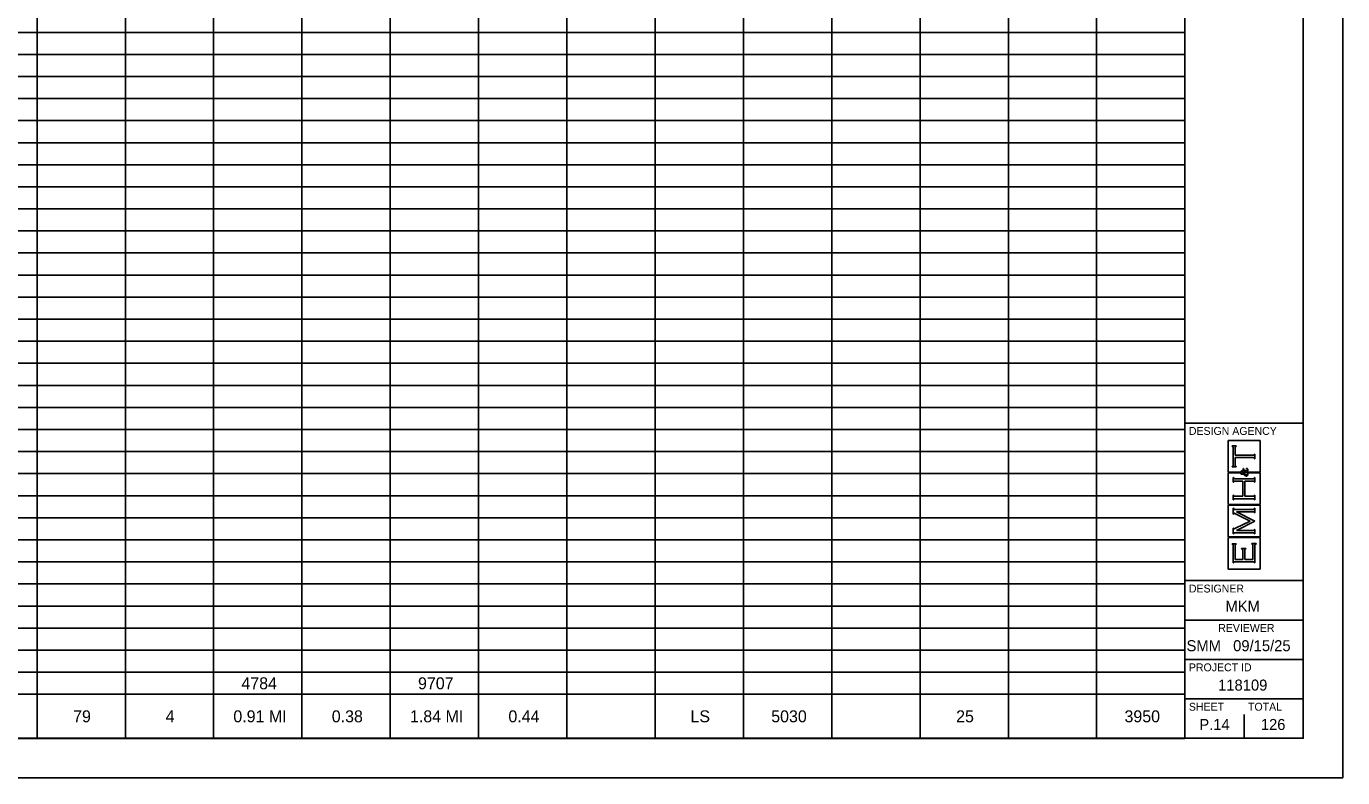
# Model space of a CAD drawing. Extents: x 0 to 34, y 0 to 22.
# Drawn here: x 17.31 to 34, y 0 to 9.53 of the extents above; entities that cross this region are included whole.
import ezdxf

# ---------------------------------------------------------------- set-up
doc = ezdxf.new("R2010")
doc.units = 0
for name, color, linetype in [('Default', 7, 'Continuous'), ('SH_Border', 7, 'Continuous'), ('SH_Cut_Line', 7, 'Continuous'), ('SH_Data', 7, 'Continuous')]:
    doc.layers.add(name, color=color, linetype=linetype)

msp = doc.modelspace()

# ---------------------------------------------------------------- linework, layer by layer
at = {"layer": 'Default'}
for p, q in [((17.442, 21.496), (17.442, 0.498)), ((18.562, 21.496), (18.562, 0.498)), ((19.681, 21.496), (19.681, 0.498)), ((20.801, 21.496), (20.801, 0.498)), ((21.921, 21.496), (21.921, 0.498)), ((23.041, 21.496), (23.041, 0.498)), ((24.161, 21.496), (24.161, 0.498)), ((25.281, 21.496), (25.281, 0.498)), ((26.401, 21.496), (26.401, 0.498)), ((27.521, 21.496), (27.521, 0.498)), ((28.64, 21.496), (28.64, 0.498)), ((29.76, 21.496), (29.76, 0.498)), ((30.88, 21.496), (30.88, 0.498)), ((32, 21.496), (32, 0.498)), ((1.5, 9.457), (32, 9.457)), ((1.5, 9.177), (32, 9.177)), ((1.5, 8.897), (32, 8.897)), ((1.5, 8.617), (32, 8.617)), ((1.5, 8.337), (32, 8.337)), ((1.5, 8.057), (32, 8.057)), ((1.5, 7.777), (32, 7.777)), ((1.5, 7.498), (32, 7.498)), ((1.5, 7.218), (32, 7.218)), ((1.5, 6.938), (32, 6.938)), ((1.5, 6.658), (32, 6.658)), ((1.5, 6.378), (32, 6.378)), ((1.5, 6.098), (32, 6.098)), ((1.5, 5.818), (32, 5.818)), ((1.5, 5.538), (32, 5.538)), ((1.5, 5.258), (32, 5.258)), ((1.5, 4.978), (32, 4.978)), ((1.5, 4.698), (32, 4.698)), ((1.5, 4.418), (32, 4.418)), ((1.5, 4.138), (32, 4.138)), ((1.5, 3.858), (32, 3.858)), ((1.5, 3.578), (32, 3.578)), ((1.5, 3.298), (32, 3.298)), ((1.5, 3.018), (32, 3.018)), ((1.5, 2.738), (32, 2.738)), ((1.5, 2.458), (32, 2.458)), ((1.5, 2.178), (32, 2.178)), ((1.5, 1.898), (32, 1.898)), ((1.5, 1.618), (32, 1.618)), ((1.5, 1.338), (32, 1.338)), ((1.5, 1.058), (32, 1.058)), ((1.5, 0.498), (32, 0.498))]:
    msp.add_line(p, q, dxfattribs=at)
at = {"layer": 'SH_Border'}
for p, q in [((32, 0.5), (32, 21.5)), ((32, 4.5), (33.5, 4.5)), ((32, 2.5), (33.5, 2.5)), ((32, 2), (33.5, 2)), ((32, 1.5), (33.5, 1.5)), ((32, 1), (33.5, 1))]:
    msp.add_line(p, q, dxfattribs=at)
msp.add_lwpolyline([(1.5, 21.5), (33.5, 21.5), (33.5, 0.5), (1.5, 0.5)], close=True, dxfattribs=at)
at = {"layer": 'SH_Cut_Line'}
msp.add_lwpolyline([(0, 0), (34, 0), (34, 22), (0, 22)], close=True, dxfattribs=at)
at = {"layer": 'SH_Data'}
for p, q in [((32.952, 4.279), (32.547, 4.279)), ((32.547, 4.279), (32.547, 3.875)), ((32.598, 4.204), (32.598, 4.211)), ((32.598, 4.211), (32.65, 4.211)), ((32.603, 4.203), (32.598, 4.204)), ((32.606, 4.201), (32.603, 4.203)), ((32.608, 4.199), (32.606, 4.201)), ((32.61, 4.196), (32.608, 4.199)), ((32.611, 4.192), (32.61, 4.196)), ((32.611, 4.187), (32.611, 4.192)), ((32.611, 3.968), (32.611, 4.187)), ((32.638, 4.196), (32.637, 4.192)), ((32.637, 4.192), (32.637, 4.187)), ((32.637, 4.187), (32.637, 4.093)), ((32.64, 4.199), (32.638, 4.196)), ((32.642, 4.201), (32.64, 4.199)), ((32.645, 4.203), (32.642, 4.201)), ((32.65, 4.204), (32.645, 4.203)), ((32.65, 4.211), (32.65, 4.204)), ((32.952, 3.875), (32.952, 4.279)), ((32.637, 4.093), (32.864, 4.093)), ((32.864, 4.061), (32.637, 4.061)), ((32.637, 4.061), (32.637, 3.968)), ((32.864, 4.093), (32.869, 4.093)), ((32.87, 4.061), (32.864, 4.061)), ((32.869, 4.093), (32.873, 4.094)), ((32.874, 4.06), (32.87, 4.061)), ((32.873, 4.094), (32.876, 4.096)), ((32.876, 4.059), (32.874, 4.06)), ((32.876, 4.096), (32.878, 4.097)), ((32.878, 4.057), (32.876, 4.059)), ((32.878, 4.097), (32.88, 4.101)), ((32.88, 4.053), (32.878, 4.057)), ((32.88, 4.101), (32.881, 4.106)), ((32.881, 4.048), (32.88, 4.053)), ((32.881, 4.106), (32.888, 4.106)), ((32.888, 4.048), (32.881, 4.048)), ((32.888, 4.106), (32.888, 4.048)), ((32.547, 3.875), (32.696, 3.875)), ((32.696, 3.869), (32.547, 3.869)), ((32.547, 3.869), (32.547, 3.465)), ((32.598, 3.95), (32.603, 3.951)), ((32.598, 3.944), (32.598, 3.95)), ((32.65, 3.944), (32.598, 3.944)), ((32.603, 3.951), (32.606, 3.953)), ((32.606, 3.953), (32.608, 3.955)), ((32.608, 3.955), (32.61, 3.958)), ((32.61, 3.958), (32.611, 3.962)), ((32.611, 3.962), (32.611, 3.968)), ((32.637, 3.968), (32.637, 3.962)), ((32.637, 3.962), (32.638, 3.958)), ((32.638, 3.958), (32.64, 3.955)), ((32.64, 3.955), (32.642, 3.953)), ((32.642, 3.953), (32.645, 3.951)), ((32.645, 3.951), (32.65, 3.95)), ((32.65, 3.95), (32.65, 3.944)), ((32.696, 3.875), (32.696, 3.869)), ((32.703, 3.879), (32.705, 3.883)), ((32.703, 3.873), (32.703, 3.879)), ((32.703, 3.868), (32.703, 3.873)), ((32.705, 3.863), (32.703, 3.868)), ((32.705, 3.883), (32.708, 3.887)), ((32.708, 3.858), (32.705, 3.863)), ((32.708, 3.887), (32.711, 3.89)), ((32.709, 3.879), (32.708, 3.876)), ((32.708, 3.876), (32.708, 3.873)), ((32.708, 3.873), (32.708, 3.869)), ((32.708, 3.869), (32.71, 3.866)), ((32.712, 3.853), (32.708, 3.858)), ((32.712, 3.881), (32.709, 3.879)), ((32.71, 3.866), (32.712, 3.864)), ((32.711, 3.89), (32.715, 3.892)), ((32.714, 3.883), (32.712, 3.881)), ((32.712, 3.864), (32.715, 3.862)), ((32.718, 3.85), (32.712, 3.853)), ((32.716, 3.884), (32.714, 3.883)), ((32.715, 3.892), (32.72, 3.892)), ((32.715, 3.862), (32.718, 3.861)), ((32.72, 3.884), (32.716, 3.884)), ((32.718, 3.861), (32.721, 3.861)), ((32.726, 3.85), (32.718, 3.85)), ((32.72, 3.892), (32.725, 3.892)), ((32.724, 3.884), (32.72, 3.884)), ((32.721, 3.861), (32.723, 3.861)), ((32.723, 3.861), (32.725, 3.862)), ((32.728, 3.882), (32.724, 3.884)), ((32.725, 3.892), (32.729, 3.89)), ((32.725, 3.862), (32.728, 3.862)), ((32.729, 3.85), (32.726, 3.85)), ((32.731, 3.88), (32.728, 3.882)), ((32.728, 3.862), (32.731, 3.863)), ((32.729, 3.89), (32.732, 3.887)), ((32.731, 3.85), (32.729, 3.85)), ((32.734, 3.877), (32.731, 3.88)), ((32.731, 3.863), (32.735, 3.865)), ((32.734, 3.851), (32.731, 3.85)), ((32.732, 3.887), (32.736, 3.883)), ((32.737, 3.872), (32.734, 3.877)), ((32.737, 3.852), (32.734, 3.851)), ((32.735, 3.865), (32.74, 3.867)), ((32.736, 3.883), (32.74, 3.878)), ((32.74, 3.867), (32.737, 3.872)), ((32.741, 3.853), (32.737, 3.852)), ((32.738, 3.893), (32.738, 3.922)), ((32.738, 3.922), (32.741, 3.922)), ((32.741, 3.893), (32.738, 3.893)), ((32.74, 3.878), (32.744, 3.869)), ((32.741, 3.922), (32.741, 3.918)), ((32.741, 3.918), (32.742, 3.915)), ((32.742, 3.896), (32.741, 3.895)), ((32.741, 3.895), (32.741, 3.893)), ((32.746, 3.855), (32.741, 3.853)), ((32.742, 3.915), (32.743, 3.913)), ((32.743, 3.897), (32.742, 3.896)), ((32.743, 3.913), (32.745, 3.911)), ((32.745, 3.899), (32.743, 3.897)), ((32.744, 3.869), (32.754, 3.875)), ((32.745, 3.911), (32.749, 3.908)), ((32.746, 3.899), (32.745, 3.899)), ((32.748, 3.899), (32.746, 3.899)), ((32.752, 3.844), (32.746, 3.855)), ((32.755, 3.899), (32.748, 3.899)), ((32.749, 3.908), (32.756, 3.904)), ((32.756, 3.86), (32.751, 3.857)), ((32.751, 3.857), (32.754, 3.852)), ((32.757, 3.837), (32.752, 3.844)), ((32.754, 3.875), (32.764, 3.881)), ((32.754, 3.852), (32.757, 3.848)), ((32.763, 3.895), (32.755, 3.899)), ((32.756, 3.904), (32.763, 3.9)), ((32.761, 3.863), (32.756, 3.86)), ((32.757, 3.848), (32.761, 3.845)), ((32.764, 3.865), (32.761, 3.863)), ((32.761, 3.845), (32.765, 3.843)), ((32.763, 3.9), (32.77, 3.896)), ((32.772, 3.887), (32.763, 3.895)), ((32.764, 3.881), (32.772, 3.887)), ((32.768, 3.867), (32.764, 3.865)), ((32.765, 3.843), (32.769, 3.841)), ((32.774, 3.872), (32.768, 3.867)), ((32.769, 3.841), (32.773, 3.841)), ((32.77, 3.896), (32.776, 3.891)), ((32.773, 3.841), (32.778, 3.841)), ((32.782, 3.878), (32.774, 3.872)), ((32.776, 3.891), (32.781, 3.895)), ((32.778, 3.841), (32.782, 3.843)), ((32.779, 3.923), (32.781, 3.926)), ((32.782, 3.922), (32.779, 3.923)), ((32.781, 3.926), (32.787, 3.924)), ((32.781, 3.895), (32.784, 3.898)), ((32.785, 3.921), (32.782, 3.922)), ((32.786, 3.873), (32.782, 3.878)), ((32.782, 3.843), (32.786, 3.846)), ((32.784, 3.898), (32.786, 3.901)), ((32.786, 3.919), (32.785, 3.921)), ((32.788, 3.917), (32.786, 3.919)), ((32.786, 3.901), (32.788, 3.904)), ((32.791, 3.886), (32.786, 3.881)), ((32.786, 3.881), (32.791, 3.876)), ((32.788, 3.869), (32.786, 3.873)), ((32.786, 3.846), (32.789, 3.849)), ((32.787, 3.924), (32.792, 3.921)), ((32.789, 3.914), (32.788, 3.917)), ((32.788, 3.904), (32.789, 3.908)), ((32.79, 3.867), (32.788, 3.869)), ((32.789, 3.911), (32.789, 3.914)), ((32.789, 3.908), (32.789, 3.911)), ((32.789, 3.849), (32.791, 3.853)), ((32.791, 3.864), (32.79, 3.867)), ((32.794, 3.89), (32.791, 3.886)), ((32.791, 3.876), (32.795, 3.87)), ((32.791, 3.861), (32.791, 3.864)), ((32.791, 3.859), (32.791, 3.861)), ((32.791, 3.853), (32.791, 3.859)), ((32.792, 3.921), (32.795, 3.918)), ((32.796, 3.894), (32.794, 3.89)), ((32.795, 3.918), (32.798, 3.914)), ((32.795, 3.87), (32.797, 3.866)), ((32.798, 3.897), (32.796, 3.894)), ((32.797, 3.866), (32.798, 3.861)), ((32.799, 3.844), (32.797, 3.838)), ((32.798, 3.914), (32.799, 3.91)), ((32.799, 3.901), (32.798, 3.897)), ((32.798, 3.861), (32.799, 3.857)), ((32.799, 3.91), (32.799, 3.905)), ((32.799, 3.905), (32.799, 3.901)), ((32.803, 3.869), (32.799, 3.875)), ((32.799, 3.875), (32.952, 3.875)), ((32.799, 3.857), (32.799, 3.852)), ((32.799, 3.852), (32.799, 3.844)), ((32.952, 3.869), (32.803, 3.869)), ((32.952, 3.465), (32.952, 3.869)), ((32.611, 3.749), (32.611, 3.807)), ((32.611, 3.807), (32.617, 3.807)), ((32.617, 3.749), (32.611, 3.749)), ((32.617, 3.807), (32.619, 3.802)), ((32.618, 3.754), (32.617, 3.749)), ((32.62, 3.758), (32.618, 3.754)), ((32.619, 3.802), (32.62, 3.798)), ((32.62, 3.798), (32.623, 3.797)), ((32.623, 3.76), (32.62, 3.758)), ((32.623, 3.797), (32.625, 3.795)), ((32.625, 3.761), (32.623, 3.76)), ((32.625, 3.795), (32.629, 3.794)), ((32.629, 3.762), (32.625, 3.761)), ((32.629, 3.794), (32.635, 3.794)), ((32.635, 3.762), (32.629, 3.762)), ((32.635, 3.794), (32.864, 3.794)), ((32.732, 3.762), (32.635, 3.762)), ((32.732, 3.572), (32.732, 3.762)), ((32.763, 3.833), (32.757, 3.837)), ((32.864, 3.762), (32.759, 3.762)), ((32.759, 3.762), (32.759, 3.572)), ((32.768, 3.829), (32.763, 3.833)), ((32.774, 3.827), (32.768, 3.829)), ((32.779, 3.827), (32.774, 3.827)), ((32.785, 3.827), (32.779, 3.827)), ((32.79, 3.829), (32.785, 3.827)), ((32.793, 3.834), (32.79, 3.829)), ((32.797, 3.838), (32.793, 3.834)), ((32.864, 3.794), (32.869, 3.794)), ((32.87, 3.762), (32.864, 3.762)), ((32.869, 3.794), (32.873, 3.795)), ((32.874, 3.761), (32.87, 3.762)), ((32.873, 3.795), (32.876, 3.797)), ((32.876, 3.76), (32.874, 3.761)), ((32.876, 3.797), (32.878, 3.798)), ((32.878, 3.758), (32.876, 3.76)), ((32.878, 3.798), (32.88, 3.802)), ((32.88, 3.754), (32.878, 3.758)), ((32.88, 3.802), (32.881, 3.807)), ((32.881, 3.749), (32.88, 3.754)), ((32.881, 3.807), (32.888, 3.807)), ((32.888, 3.749), (32.881, 3.749)), ((32.888, 3.807), (32.888, 3.749)), ((32.611, 3.527), (32.611, 3.585)), ((32.611, 3.585), (32.617, 3.585)), ((32.617, 3.527), (32.611, 3.527)), ((32.617, 3.585), (32.619, 3.58)), ((32.618, 3.532), (32.617, 3.527)), ((32.62, 3.536), (32.618, 3.532)), ((32.619, 3.58), (32.62, 3.576)), ((32.62, 3.576), (32.623, 3.574)), ((32.623, 3.537), (32.62, 3.536)), ((32.623, 3.574), (32.625, 3.573)), ((32.625, 3.539), (32.623, 3.537)), ((32.625, 3.573), (32.629, 3.572)), ((32.629, 3.54), (32.625, 3.539)), ((32.629, 3.572), (32.635, 3.572)), ((32.635, 3.54), (32.629, 3.54)), ((32.635, 3.572), (32.732, 3.572)), ((32.864, 3.54), (32.635, 3.54)), ((32.759, 3.572), (32.864, 3.572)), ((32.864, 3.572), (32.87, 3.572)), ((32.87, 3.54), (32.864, 3.54)), ((32.87, 3.572), (32.874, 3.573)), ((32.874, 3.539), (32.87, 3.54)), ((32.874, 3.573), (32.876, 3.574)), ((32.876, 3.538), (32.874, 3.539)), ((32.876, 3.574), (32.878, 3.576)), ((32.878, 3.536), (32.876, 3.538)), ((32.878, 3.576), (32.88, 3.58)), ((32.88, 3.532), (32.878, 3.536)), ((32.88, 3.58), (32.881, 3.585)), ((32.881, 3.527), (32.88, 3.532)), ((32.881, 3.585), (32.888, 3.585)), ((32.888, 3.527), (32.881, 3.527)), ((32.888, 3.585), (32.888, 3.527)), ((32.547, 3.465), (32.952, 3.465)), ((32.952, 3.459), (32.547, 3.459)), ((32.547, 3.459), (32.547, 3.055)), ((32.611, 3.345), (32.611, 3.418)), ((32.611, 3.418), (32.617, 3.418)), ((32.617, 3.345), (32.611, 3.345)), ((32.617, 3.418), (32.619, 3.412)), ((32.62, 3.352), (32.617, 3.345)), ((32.619, 3.412), (32.62, 3.409)), ((32.62, 3.409), (32.623, 3.407)), ((32.622, 3.355), (32.62, 3.352)), ((32.626, 3.355), (32.622, 3.355)), ((32.623, 3.407), (32.625, 3.405)), ((32.625, 3.405), (32.629, 3.405)), ((32.629, 3.355), (32.626, 3.355)), ((32.629, 3.405), (32.635, 3.405)), ((32.633, 3.353), (32.629, 3.355)), ((32.64, 3.35), (32.633, 3.353)), ((32.635, 3.405), (32.864, 3.405)), ((32.825, 3.257), (32.64, 3.35)), ((32.864, 3.373), (32.654, 3.373)), ((32.654, 3.373), (32.888, 3.255)), ((32.75, 3.5), (32.75, 3.5)), ((32.864, 3.405), (32.869, 3.405)), ((32.87, 3.373), (32.864, 3.373)), ((32.869, 3.405), (32.873, 3.405)), ((32.874, 3.372), (32.87, 3.373)), ((32.873, 3.405), (32.876, 3.407)), ((32.876, 3.37), (32.874, 3.372)), ((32.876, 3.407), (32.878, 3.409)), ((32.878, 3.369), (32.876, 3.37)), ((32.878, 3.409), (32.88, 3.412)), ((32.88, 3.365), (32.878, 3.369)), ((32.88, 3.412), (32.881, 3.418)), ((32.881, 3.36), (32.88, 3.365)), ((32.881, 3.418), (32.888, 3.418)), ((32.888, 3.36), (32.881, 3.36)), ((32.888, 3.418), (32.888, 3.36)), ((32.952, 3.055), (32.952, 3.459)), ((32.641, 3.165), (32.825, 3.257)), ((32.888, 3.255), (32.654, 3.138)), ((32.547, 3.055), (32.952, 3.055)), ((32.952, 3.049), (32.547, 3.049)), ((32.547, 3.049), (32.547, 2.645)), ((32.611, 3.096), (32.611, 3.168)), ((32.611, 3.168), (32.617, 3.168)), ((32.617, 3.096), (32.611, 3.096)), ((32.617, 3.168), (32.62, 3.162)), ((32.618, 3.102), (32.617, 3.096)), ((32.62, 3.105), (32.618, 3.102)), ((32.62, 3.162), (32.622, 3.158)), ((32.623, 3.107), (32.62, 3.105)), ((32.622, 3.158), (32.626, 3.158)), ((32.625, 3.109), (32.623, 3.107)), ((32.629, 3.109), (32.625, 3.109)), ((32.626, 3.158), (32.627, 3.158)), ((32.627, 3.158), (32.633, 3.161)), ((32.635, 3.109), (32.629, 3.109)), ((32.633, 3.161), (32.641, 3.165)), ((32.864, 3.109), (32.635, 3.109)), ((32.654, 3.138), (32.864, 3.138)), ((32.864, 3.138), (32.869, 3.138)), ((32.87, 3.109), (32.864, 3.109)), ((32.869, 3.138), (32.873, 3.139)), ((32.874, 3.109), (32.87, 3.109)), ((32.873, 3.139), (32.876, 3.141)), ((32.876, 3.107), (32.874, 3.109)), ((32.876, 3.141), (32.878, 3.143)), ((32.878, 3.105), (32.876, 3.107)), ((32.878, 3.143), (32.88, 3.146)), ((32.88, 3.102), (32.878, 3.105)), ((32.88, 3.146), (32.881, 3.151)), ((32.881, 3.096), (32.88, 3.102)), ((32.881, 3.151), (32.888, 3.151)), ((32.888, 3.096), (32.881, 3.096)), ((32.888, 3.151), (32.888, 3.096)), ((32.952, 2.645), (32.952, 3.049)), ((32.598, 2.962), (32.598, 2.969)), ((32.598, 2.969), (32.65, 2.969)), ((32.603, 2.961), (32.598, 2.962)), ((32.606, 2.959), (32.603, 2.961)), ((32.608, 2.957), (32.606, 2.959)), ((32.61, 2.955), (32.608, 2.957)), ((32.611, 2.951), (32.61, 2.955)), ((32.611, 2.945), (32.611, 2.951)), ((32.611, 2.725), (32.611, 2.945)), ((32.64, 2.957), (32.638, 2.955)), ((32.638, 2.955), (32.638, 2.951)), ((32.638, 2.951), (32.638, 2.945)), ((32.638, 2.945), (32.638, 2.77)), ((32.642, 2.959), (32.64, 2.957)), ((32.645, 2.961), (32.642, 2.959)), ((32.65, 2.962), (32.645, 2.961)), ((32.65, 2.969), (32.65, 2.962)), ((32.719, 2.902), (32.719, 2.908)), ((32.719, 2.908), (32.772, 2.908)), ((32.724, 2.901), (32.719, 2.902)), ((32.728, 2.899), (32.724, 2.901)), ((32.729, 2.896), (32.728, 2.899)), ((32.731, 2.894), (32.729, 2.896)), ((32.732, 2.89), (32.731, 2.894)), ((32.732, 2.884), (32.732, 2.89)), ((32.732, 2.77), (32.732, 2.884)), ((32.76, 2.894), (32.759, 2.89)), ((32.759, 2.89), (32.759, 2.884)), ((32.759, 2.884), (32.759, 2.77)), ((32.761, 2.896), (32.76, 2.894)), ((32.763, 2.899), (32.761, 2.896)), ((32.767, 2.901), (32.763, 2.899)), ((32.772, 2.902), (32.767, 2.901)), ((32.772, 2.908), (32.772, 2.902)), ((32.848, 2.965), (32.848, 2.972)), ((32.848, 2.972), (32.901, 2.972)), ((32.853, 2.964), (32.848, 2.965)), ((32.857, 2.962), (32.853, 2.964)), ((32.859, 2.96), (32.857, 2.962)), ((32.86, 2.958), (32.859, 2.96)), ((32.861, 2.953), (32.86, 2.958)), ((32.861, 2.948), (32.861, 2.953)), ((32.861, 2.77), (32.861, 2.948)), ((32.889, 2.957), (32.888, 2.953)), ((32.888, 2.953), (32.888, 2.948)), ((32.888, 2.948), (32.888, 2.725)), ((32.891, 2.96), (32.889, 2.957)), ((32.892, 2.962), (32.891, 2.96)), ((32.896, 2.964), (32.892, 2.962)), ((32.901, 2.965), (32.896, 2.964)), ((32.901, 2.972), (32.901, 2.965)), ((32.617, 2.725), (32.611, 2.725)), ((32.619, 2.73), (32.617, 2.725)), ((32.62, 2.734), (32.619, 2.73)), ((32.623, 2.735), (32.62, 2.734)), ((32.625, 2.737), (32.623, 2.735)), ((32.629, 2.738), (32.625, 2.737)), ((32.635, 2.738), (32.629, 2.738)), ((32.864, 2.738), (32.635, 2.738)), ((32.638, 2.77), (32.732, 2.77)), ((32.759, 2.77), (32.861, 2.77)), ((32.87, 2.738), (32.864, 2.738)), ((32.874, 2.737), (32.87, 2.738)), ((32.876, 2.735), (32.874, 2.737)), ((32.878, 2.734), (32.876, 2.735)), ((32.88, 2.73), (32.878, 2.734)), ((32.881, 2.725), (32.88, 2.73)), ((32.888, 2.725), (32.881, 2.725)), ((32.547, 2.645), (32.952, 2.645)), ((32.375, 0.675), (32.375, 0.675)), ((32.75, 0.5), (32.75, 0.8))]:
    msp.add_line(p, q, dxfattribs=at)

# ---------------------------------------------------------------- texts
at = {"layer": 'Default'}
for s, height, p in [('4784', 0.1515, (20.034, 1.122)), ('9707', 0.1515, (22.274, 1.122)), ('79', 0.1515, (17.9, 0.703)), ('4', 0.152, (19.073, 0.703)), ('0.91 MI', 0.1515, (19.932, 0.703)), ('0.38', 0.1515, (21.18, 0.703)), ('1.84 MI', 0.1515, (22.172, 0.703)), ('0.44', 0.1515, (23.42, 0.703)), ('LS', 0.1515, (25.729, 0.703)), ('5030', 0.1515, (26.753, 0.703)), ('25', 0.1515, (29.098, 0.703)), ('3950', 0.1515, (31.233, 0.703))]:
    msp.add_text(s, height=height, dxfattribs=at).set_placement(p)
at = {"layer": 'SH_Data'}
for s, height, p in [('DESIGN AGENCY', 0.1, (32.05, 4.35)), ('DESIGNER', 0.1, (32.05, 2.35)), ('MKM', 0.14, (32.513, 2.105)), ('REVIEWER', 0.1, (32.422, 1.85)), ('SMM', 0.14, (32.02, 1.605)), ('09/15/25', 0.14, (32.611, 1.605)), ('PROJECT ID', 0.1, (32.05, 1.35)), ('118109', 0.14, (32.42, 1.105)), ('SHEET', 0.1, (32.05, 0.85)), ('TOTAL', 0.1, (32.8, 0.85)), ('P.14', 0.14, (32.182, 0.605)), ('126', 0.14, (32.962, 0.605))]:
    msp.add_text(s, height=height, dxfattribs=at).set_placement(p)

doc.saveas('drawing.dxf')
